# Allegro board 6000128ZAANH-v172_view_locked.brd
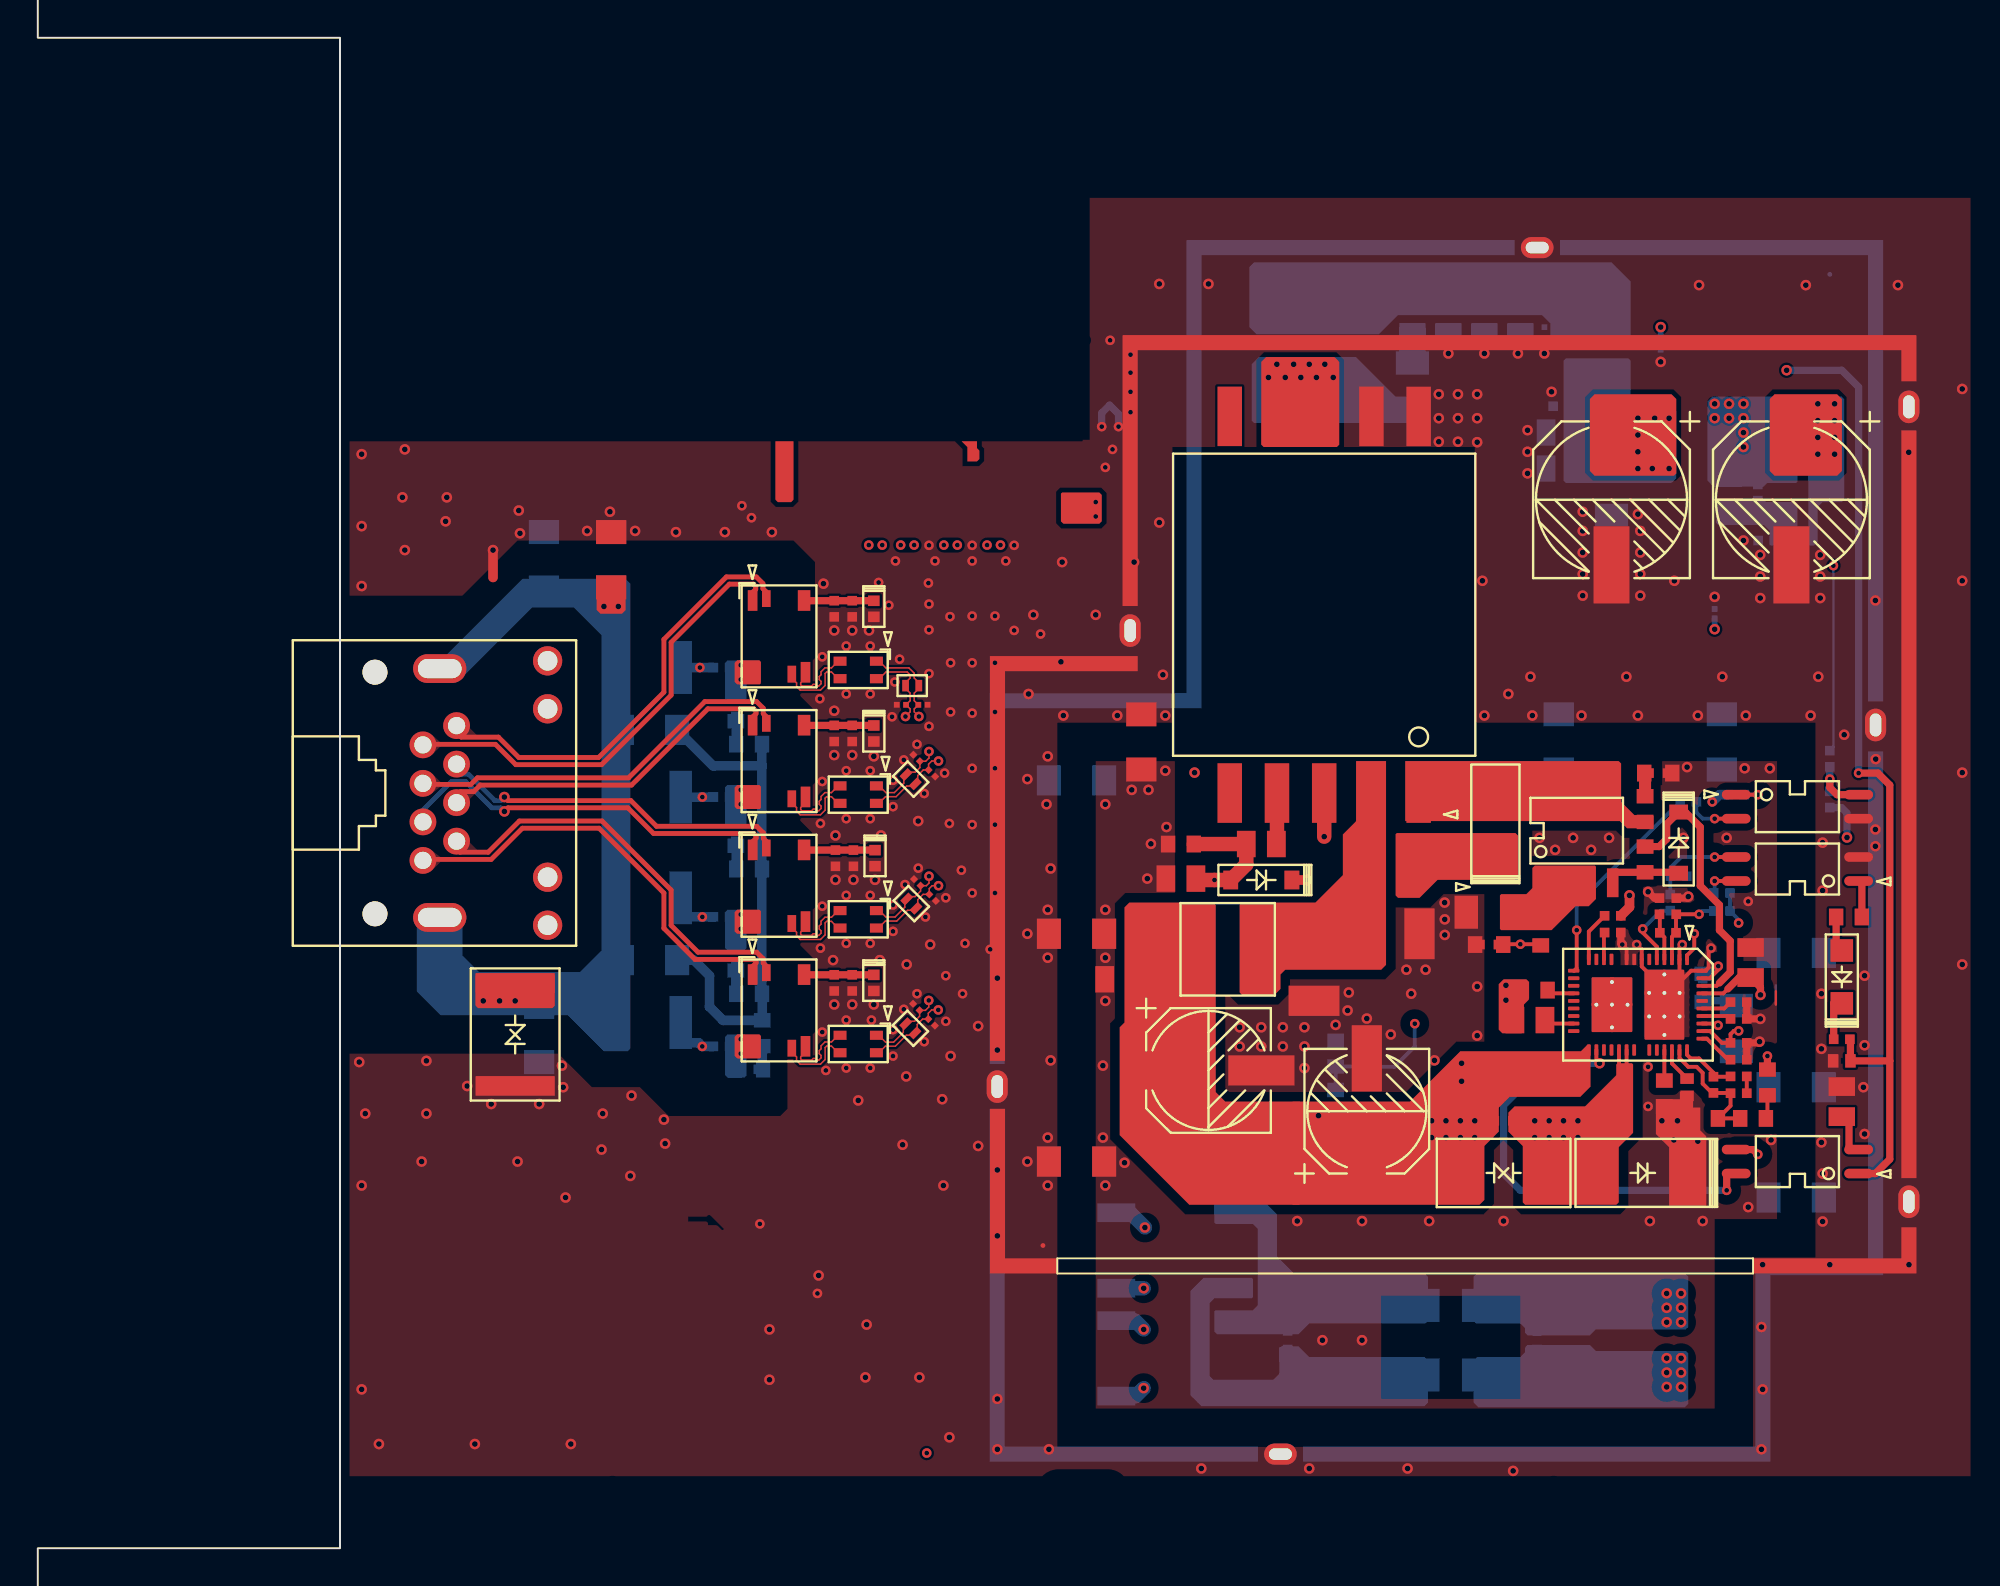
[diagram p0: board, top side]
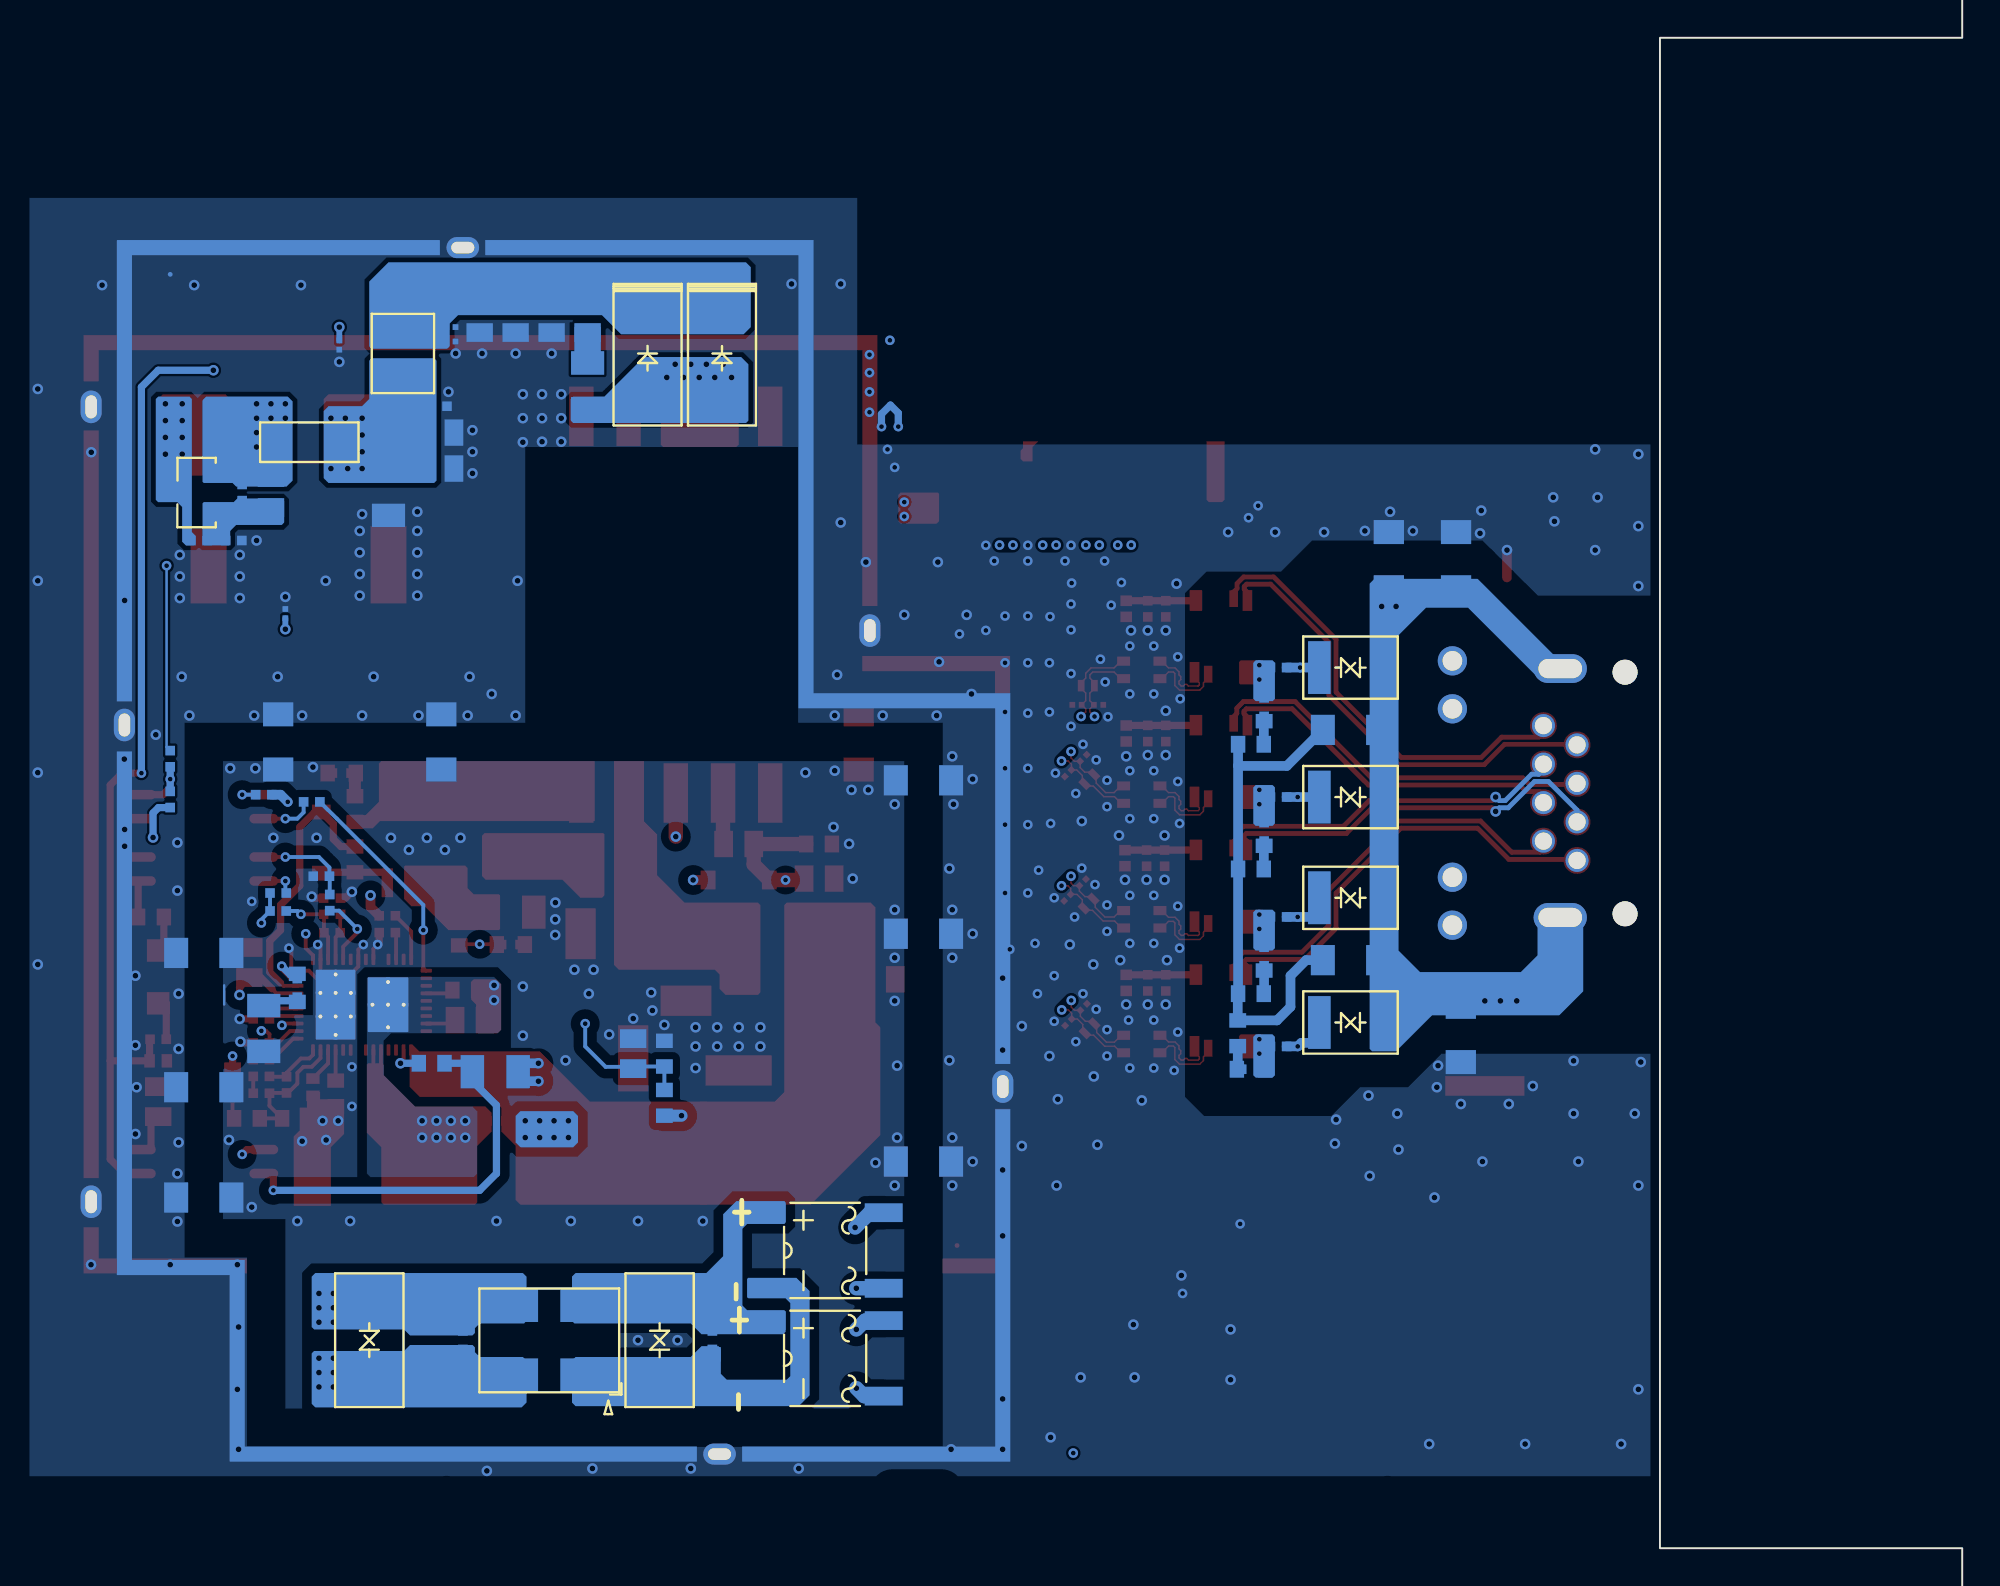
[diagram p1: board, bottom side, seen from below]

Outline 181 x 100 mm; copper layers: TOP, L2, L3, L4, L5, BOTTOM. Coordinates in mm from the lower left corner of the outline.

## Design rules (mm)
constraint set DEFAULT: min track width 0.127
net group 5G_PCIE_RX0: nets 5G_PCIE_RX0_N 5G_PCIE_RX0_P
net group 5G_PCIE_RX_1: nets N17591241 N17591244
net group 5G_PCIE_TX0: nets 5G_PCIE_TX0_N 5G_PCIE_TX0_P
net group 5G_PCIE_TX0-2: nets N5381196 N5381250
net group 5G_PCIE_TX_1: nets N17578663 N17578680
net group GTP_A: nets GTP_AN GTP_AP
net group GTP_B: nets GTP_BN GTP_BP
net group GTP_C: nets GTP_CN GTP_CP
net group GTP_D: nets GTP_DN GTP_DP
net group M_D: nets M_DM M_DP
net group M_DP: nets M_DP+ M_DP-
net group MDI_CH0: nets MDI_CH0_N MDI_CH0_P
net group MDI_CH1: nets MDI_CH1_N MDI_CH1_P
net group MDI_CH2: nets MDI_CH2_N MDI_CH2_P
net group MDI_CH3: nets MDI_CH3_N MDI_CH3_P
net group MDI_CH3_TRX0: nets MDI_CH3_TRXN0 MDI_CH3_TRXP0
net group MDI_CH3_TRX1: nets MDI_CH3_TRXN1 MDI_CH3_TRXP1
net group MDI_CH3_TRX2: nets MDI_CH3_TRXN2 MDI_CH3_TRXP2
net group MDI_CH3_TRX3: nets MDI_CH3_TRXN3 MDI_CH3_TRXP3
net group PCIE_HSO: nets PCIE_HSON PCIE_HSOP
net group PCIE_REFCLK: nets PCIE_REFCLK_N PCIE_REFCLK_P
net group PCIE_REFCLK-2: nets N5381146 N5381180
net group USB-PD: nets USB-PD_CC1 USB-PD_CC2
net group USB_D: nets USB_D+ USB_D-
net group EGND: nets EAR_GND
net group RF50: nets BLE_RFIO N32329 N32649 N49495 N49503
net group S15: nets N17720182 N17720684 N17720687 N17720690 N17720693 N17720696

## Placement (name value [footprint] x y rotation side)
C6  1000 PF/2KV  [C1206-0160]  26.8 62.36 90 bottom
C11  1000 PF/2KV  [C1206-0160]  30.35 62.36 90 top
C24  1000 PF/2KV  [C1206-0160]  26.54 37.21 270 bottom
C25  2200 PF/2KV  [C1206-0160]  32.38 41.15 180 bottom
C26  2200 PF/2KV  [C1206-0160]  32.38 53.34 180 bottom
C51  0.1 UF/25V  [C0402]  93.34 63.37 0 bottom
C61  33 PF/25V  [C0201]  80.01 73.91 180 bottom
C62  100 PF/50V  [C0201]  80.01 74.68 180 bottom
C63  2 PF/25V  [C0201]  46.86 54.67 0 top
C64  2 PF/25V  [C0201]  45.72 54.67 180 top
C65  2 PF/25V  [C0201]  46.52 51.85 135 top
C66  2 PF/25V  [C0201]  47.33 51.05 315 top
C67  2 PF/25V  [C0201]  46.56 45.27 135 top
C68  2 PF/25V  [C0201]  47.37 44.46 315 top
C69  2 PF/25V  [C0201]  46.51 38.66 135 top
C70  2 PF/25V  [C0201]  47.32 37.85 315 top
C72  1200 PF/50V  [C0603]  85.79 51.05 0 top
C75  1000 PF/2KV  [C1206-0160]  30.35 62.36 90 bottom
C82  0.1 UF/6.3V  [C0201]  88.77 59.5 90 bottom
C84  1000 PF/2KV  [C1206-0160]  93.09 34.42 0 bottom
C88  0.1 UF/6.3V  [C0201]  85.92 73.72 270 bottom
C99  1000 PF/2KV  [C1206-0160]  58.42 52.7 90 top
C100  1000 PF/2KV  [C1206-0160]  80.52 52.7 90 bottom
C101  1000 PF/2KV  [C1206-0160]  54.99 30.48 180 bottom
C102  1000 PF/2KV  [C1206-0160]  54.99 30.48 180 top
C103  1000 PF/2KV  [C1206-0160]  54.99 42.55 180 top
C104  1000 PF/2KV  [C1206-0160]  89.15 52.7 90 bottom
C105  1000 PF/2KV  [C1206-0160]  54.99 42.55 180 bottom
C106  1000 PF/2KV  [C1206-0160]  93.09 41.53 0 bottom
C215  0.01 UF/100V  [C0603]  66.17 21.02 270 bottom
C218  0.01 UF/100V  [C0603]  79.38 21.02 270 bottom
C236  22UF/63V  [CES-0630-P-0850-G]  61.98 35.31 0 top
C238  0.01 UF/100V  [C0603]  36.96 54.55 90 bottom
C243  22UF/63V  [CES-0630-P-0850-G]  70.36 33.15 90 top
C335  1000 PF/2KV  [C1206-0160]  93.09 28.57 0 bottom
C338  1000 PF/2KV  [C1206-0160]  54.99 50.67 180 bottom
C339  2200 PF/100V  [C0805]  72.77 75.18 90 bottom
C340  22 UF/25V  [C0805]  78.49 75.18 270 bottom
C343  22 UF/25V  [C0805]  76.58 75.18 270 bottom
C344  22 UF/25V  [C0805]  74.68 75.18 270 bottom
C358  0.1 UF/25V  [C0402]  80.64 70.48 180 bottom
C360  22 UF/25V  [C0805]  80.64 69.09 180 bottom
C361  0.01 UF/100V  [C0603]  36.96 47.94 90 bottom
C362  22 UF/25V  [C0805]  80.64 67.18 180 bottom
C363  0.01 UF/100V  [C0603]  36.96 41.34 90 bottom
C367  0.01 UF/100V  [C0603]  37.66 35.37 180 bottom
C371  0.1 UF/100V  [C0603]  77.6 32.64 180 top
C374  0.1 UF/100V  [C0805]  70.36 36.2 270 bottom
C375  0.1 UF/100V  [C0805]  57.28 40.13 0 top
C376  2.2 UF/100V  [C1210]  67.56 40.39 90 top
C377  2.2 UF/100V  [C1210]  71.75 42.55 180 top
C378  0.1 UF/100V  [C0805]  71.63 47.12 180 top
C379  4.7 UF/25V  [C0805]  90.68 41.02 270 top
C400  0.1 UF/16V  [C0402]  42.16 59.76 90 top
C401  0.1 UF/16V  [C0402]  42.16 53.15 90 top
C402  0.1 UF/16V  [C0402]  42.23 46.55 90 top
C403  0.1 UF/16V  [C0402]  42.16 39.94 90 top
C410  4700 PF/50V  [C0402]  90.04 34.99 0 top
C412  10 PF/50V  [C0402]  88.71 34.54 270 top
C413  0.1 UF/25V  [C0402]  90.04 36.77 0 top
C414  330 PF/50V  [C0603]  76.83 41.97 0 top
C416  4.7 UF/25V  [C0805]  60.52 45.47 180 top
C420  0.047 UF/50V  [MLCC-0120X0070]  87.31 34.42 270 top
C434  390 PF/50V  [C0402]  43.12 59.76 90 top
C449  0.1 UF/50V  [MLCC-0120X0070]  95.5 35.81 180 top
C450  390 PF/50V  [C0402]  43.12 53.15 90 top
C451  390 PF/50V  [C0402]  43.18 46.55 90 top
C452  390 PF/50V  [C0402]  43.12 39.94 90 top
C608  4.7 UF/25V  [C0805]  89.53 65.91 270 bottom
C745  0.1 UF/25V  [C0402]  90.04 38.93 0 top
C746  1000 PF/50V  [C0603]  88.14 39.68 90 bottom
C747  2200 PF/50V  [C0402]  86.74 44.01 270 top
D3  SM1200AM-C  [DOS-SMAM-SECOS]  77.16 48.55 90 top
D5  1N4148W  [DOS-SOD-123-GRANDE]  86.87 47.37 270 top
D7  SK5100BM-C  [DOS-SMBM-SECOS]  69.6 73.03 270 bottom
D8  MMSZ6V8CW-C  [DOS-SOD-123LH-SECOS]  95.5 40.26 90 top
D15  1N4148W  [DOS-SOD-123-GRANDE]  64.77 45.39 180 top
D17  SK5100BM-C  [DOS-SMBM-SECOS]  65.66 73.03 270 bottom
D25  SK5100BM-C  [DOS-SMBM-SECOS]  84.97 29.88 180 top
D53  TTB210SR-C  [BRS-TFS-SECOS]  60.2 20.06 90 bottom
D57  TTB210SR-C  [BRS-TFS-SECOS]  60.2 25.77 90 bottom
D61  AZ5525-01F.R7G  [VARS-DFN1006P2X-AMAZING]  44.26 59.76 270 top
D62  AZ5525-01F.R7G  [VARS-DFN1006P2X-AMAZING]  44.26 53.15 270 top
D63  AZ5525-01F.R7G  [VARS-DFN1006P2X-AMAZING]  44.32 46.55 270 top
D64  AZ5525-01F.R7G  [VARS-DFN1006P2X-AMAZING]  44.26 39.94 270 top
D79  BV-FA2.5UCB  [VARS-DFN1006-BENCENT]  46.29 55.69 180 top
D80  BV-FA2.5UCB  [VARS-DFN1006-BENCENT]  46.21 50.73 315 top
D81  BV-FA2.5UCB  [VARS-DFN1006-BENCENT]  46.25 44.14 315 top
D82  BV-FA2.5UCB  [VARS-DFN1006-BENCENT]  46.19 37.54 315 top
EC4  220 UF/25V  [CES-0800-P-0950-G]  92.84 65.53 270 top
EC5  220 UF/25V  [CES-0800-P-0950-G]  83.31 65.53 270 top
FB13  BBPY00321611101Y00  [FILTS-BBPY00321611]  87.5 68.58 180 bottom
FB20  HFZ1005PF-121T20  [FILTS-0402]  36.2 56.64 180 bottom
FB21  HFZ1005PF-121T20  [FILTS-0402]  36.2 49.79 180 bottom
FB22  HFZ1005PF-121T20  [FILTS-0402]  36.2 43.44 180 bottom
FB23  HFZ1005PF-121T20  [FILTS-0402]  36.2 36.58 180 bottom
L2  WCM5555FASV-142-LM  [LS-WCM5555]  74.8 21.01 0 bottom
L3  1 uH/6.2A Irms  [LS-TMIM3225]  82.55 73.28 270 bottom
L5  10 uH/2A Irms /3.12A Isat  [LS-AHP40XX]  62.99 41.72 0 top
L45  WCM2012F2SF-801-GZ  [LS-2012F2SF]  43.43 56.52 180 top
L46  WCM2012F2SF-801-GZ  [LS-2012F2SF]  43.43 49.91 180 top
L47  WCM2012F2SF-801-GZ  [LS-2012F2SF]  43.43 43.31 180 top
L48  WCM2012F2SF-801-GZ  [LS-2012F2SF]  43.43 36.71 180 top
NOREF  -  []  56.01 -10.16 0 top
NOREF#2  -  []  -8.76 -39.37 0 top
NOREF#3  -  []  154.43 -10.16 0 top
NOREF#4  -  []  195.71 -10.16 0 top
NOREF#5  -  []  -8.76 -10.16 0 top
NOREF#6  -  []  -15.88 213.36 0 top
NOREF#7  -  []  -85.6 -76.2 0 top
NOREF#8  -  []  108.71 -10.16 0 top
NOREF#9  -  []  198.12 213.36 0 top
NOREF#10  -  []  0 0 0 top
NOREF#11  -  []  -15.88 -6.35 0 top
P1  PJ-04-4026-V5112-9  [RJ45-PJ-04-4026-V511X-PIP]  17.85 50 270 top
Q3  SSG06N15V-C  [SOP8-0600-1270-9]  81.47 48.01 0 top
Q32  SMS3407-C  [SOT-23-SGD]  93.47 65.91 90 bottom
R83  20 OHM  [R0603]  85.09 49.15 90 top
R139  10 OHM  [R1206]  72.77 71.56 90 bottom
R141  2 K  [R0603]  95.89 43.43 180 top
R147  3.3 K  [R0402]  95.5 36.96 180 top
R148  4.7 K  [R0805]  95.5 33.66 90 top
R149  13.7 K  [R1206]  77.66 35.24 0 bottom
R151  11.8 K  [R0603]  81.03 35.69 0 bottom
R158  24.9 K  [R1206]  81.15 21.02 270 bottom
R172  4.7 K  [R0402]  89.92 49.91 0 bottom
R180  4.7 K  [R0402]  94.87 49.66 270 bottom
R216  10 K  [R1206]  83.31 65.91 270 bottom
R237  75 OHM  [R0603]  37.66 52.58 0 bottom
R241  0 OHM  [R0402]  94.87 51.82 90 bottom
R242  75 OHM  [R0603]  38.35 37.27 90 bottom
R243  75 OHM  [R0603]  37.66 45.98 0 bottom
R244  75 OHM  [R0603]  37.66 39.37 0 bottom
R274  0 OHM  [R1206]  74.8 22.86 0 bottom
R275  0 OHM  [R1206]  74.8 19.18 0 bottom
R291  110 K  [R0603]  68.71 33.59 270 bottom
R292  20 K  [R0603]  68.71 36.2 270 bottom
R293  60.4 K  [R0402]  85.85 44.01 270 top
R294  49.9 K  [R0603]  79.25 39.56 180 top
R296  499 K  [R0603]  86.11 34.09 90 top
R297  3.3 K  [R0603]  60.52 47.3 0 top
R298  24.9 K  [R0603]  90.81 32.77 0 top
R299  10 OHM  [R0603]  91.57 34.67 90 top
R300  4.32 K  [R0603]  88.27 32.77 0 top
R301  100 K  [R0402]  90.04 34.1 0 top
R302  0 OHM  [R0402]  90.04 35.88 180 top
R303  4.7 OHM  [R0603]  85.09 46.48 90 top
R304  0.12 OHM  [R1206]  76.83 43.69 0 top
R305  1 K  [R0603]  79.57 42.61 270 top
R306  240 K  [R0402]  86.3 42.6 0 top
R307  31.6 OHM  [R0805]  78.99 37.97 180 top
R308  10 K  [R0402]  83.38 43.5 0 top
R310  10 K  [R0402]  89.15 44.7 0 bottom
R311  100 K  [R0402]  86.87 45.59 180 bottom
R312  39 K  [R0805]  71.63 45.27 180 top
R313  3.9 OHM  [R0805]  64.77 47.3 180 top
R314  51 OHM  [R1206]  89.92 37.53 90 bottom
R315  0 OHM  [R0402]  83.38 42.61 0 top
R316  0 OHM  [R0402]  86.42 44.2 90 bottom
R317  0 OHM  [R0402]  89.15 43.75 180 bottom
R322  0 OHM  [R0402]  87.38 49.53 0 bottom
R336  0 OHM  [R0402]  90.04 38.04 0 top
R615  300 K  [R0402]  91.06 65.91 270 bottom
R616  30 K  [R0402]  91.5 63.37 180 bottom
RV22  BV-SMBJ58C2  [VARS-SMB-BENCENT]  68.96 21.02 90 bottom
RV24  BV-SMBJ58C2  [VARS-SMB-BENCENT]  84.33 21.02 90 bottom
RV31  BV-SMBJ58C2  [VARS-SMB-BENCENT]  77.6 29.88 180 top
RV35  MLVS1210H48142  [VARS-MLVS1210]  32.38 56.64 0 bottom
RV36  MLVS1210H48142  [VARS-MLVS1210]  32.38 49.78 0 bottom
RV37  MLVS1210H48142  [VARS-MLVS1210]  32.38 44.45 0 bottom
RV38  MLVS1210H48142  [VARS-MLVS1210]  32.38 37.85 0 bottom
RV51  BN362M  [VARS-BN]  25.27 37.21 90 top
SC1  POE_TOP_COVER  [SHIELD-COVER]  53.21 26.04 270 top
SC2  POE_BOT_COVER  [SHIELD-COVER]  94.87 77.47 270 bottom
SF1  POE_TOP_FRAME  [SHIELD-04825X04890-TEST]  74.93 49.4 0 top
SF2  POE_BOT_FRAME  [SHIELD-06390X04650-TEST]  74.04 46.94 180 bottom
T3  PH2512-007SR  [TRS10-PH2512-007SX]  68.1 59.97 0 top
T6  TXF453229NF-181-G  [TRS6-TXF453229]  39.24 58.3 270 top
T7  TXF453229NF-181-G  [TRS6-TXF453229]  39.24 51.69 270 top
T8  TXF453229NF-181-G  [TRS6-TXF453229]  39.24 45.09 270 top
T9  TXF453229NF-181-G  [TRS6-TXF453229]  39.24 38.48 270 top
U40  LTV-217-B-G  [SOP4-0700-1270]  93.15 49.28 270 top
U41  LTV-217-B-G  [SOP4-0700-1270]  93.15 45.97 90 top
U42  LTV-217-B-G  [SOP4-0700-1270]  93.15 30.48 90 top
U50  TPS23731RMTR  [QFN45-0700X0500-0400-VIA-H8]  84.71 38.79 270 top

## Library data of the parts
C6 C11 C24-C26 C51 C61-C70 C75 C82 C84 C88 C99-C106 C215 C218 C238 C335 C338-C340 C343 C344 C358 C360-C363 C367 C371 C374-C379 C400-C403 C410 C412-C414 C416 C420 C434 C449-C452 C608 C745-C747 = CAP-NP
C72 = CAP NP
C236 C243 = CAP
D3 D5 D7 D15 D17 D25 = DIODE_1
D8 = ZENER-DIODE
D53 D57 = MD5SBRIDGE
D61-D64 RV22 RV24 RV31 RV35-RV38 = VAR-2PIN
D79-D82 = VARISTOR
EC4 EC5 = CAP_1
FB13 FB20-FB23 = FILTER-2PIN
L2 = UT21332V-TS
L3 L5 = INDUCTOR
L45-L48 = COMMON_CHOKE_12-43
P1 = RJ45-8PIN8C+2LED+2G1-2
Q3 = MOSFET-N -8PIN
Q32 = MOSFET-P
R83 R139 R147 R149 R151 R158 R172 R180 R216 R237 R241-R244 R274 R275 R291-R294 R296-R299 R301-R308 R310-R317 R322 R336 R615 R616 = RESISTOR
R141 R148 R300 = Resistor-2
RV51 = VAR
SC1 SC2 = SHIELD-COVER
SF1 = 3-PIN_6
SF2 = 3-PIN_5
T3 = PH2512-007SR
T6-T9 = TXF453229NF-181-G
U40-U42 = LTV-817A
U50 = TPS23731_0

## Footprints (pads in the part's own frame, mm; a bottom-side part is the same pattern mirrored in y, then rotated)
BRS-TFS-SECOS
  rect 0.991x2.007 smd: AC1(-2,-3.1) AC2(2,-3.1) DC+(2,3.1) DC-(-2,3.1)
C0201
  rect 0.305x0.305 smd: 1(-0.246,0) 2(0.246,0)
C0402
  rect 0.508x0.508 smd: 1(-0.429,0) 2(0.429,0)
C0603
  custom 0.222x0.222 smd: 1(-0.681,0) 2(0.681,0)
C0805
  rect 0.991x1.397 smd: 1(-0.795,0) 2(0.795,0)
C1206-0160
  rect 1.27x1.6 smd: 1(-1.463,0) 2(1.463,0)
C1210
  rect 1.6x2.692 smd: 1(-1.39,0) 2(1.39,0)
CES-0630-P-0850-G
  rect 3.505x1.6 smd: 1(-2.8,0) 2(2.8,0)
CES-0800-P-0950-G
  rect 4.089x1.905 smd: 1(-3.45,0) 2(3.45,0)
DOS-SMAM-SECOS
  rect 1.6x1.803 smd: A(1.9,0) C(-1.9,0)
DOS-SMBM-SECOS
  rect 1.803x2.54 smd: A(2.4,0) C(-2.4,0)
DOS-SOD-123-GRANDE
  rect 0.787x0.991 smd: A(1.62,0) C(-1.62,0)
DOS-SOD-123LH-SECOS
  rect 1.194x1.194 smd: A(1.4,0) C(-1.4,0)
FILTS-0402
  rect 0.508x0.508 smd: 1(-0.429,0) 2(0.429,0)
FILTS-BBPY00321611
  rect 1.245x1.6 smd: 1(-1.725,0) 2(1.725,0)
LS-2012F2SF
  rect 0.686x0.483 smd: 1(-0.962,-0.463) 2(0.962,-0.463) 3(0.962,0.463) 4(-0.962,0.463)
LS-AHP40XX
  rect 1.499x4.394 smd: 1(-1.5,0) 2(1.5,0)
LS-TMIM3225
  rect 1.499x2.794 smd: 1(-1.1,0) 2(1.1,0)
LS-WCM5555
  rect 1.803x1.194 smd: 1(-2.55,1.55) 2(-2.55,-1.55) 3(2.55,-1.55) 4(2.55,1.55)
MLCC-0120X0070
  rect 0.559x0.711 smd: 1(-0.457,0) 2(0.457,0)
QFN45-0700X0500-0400-VIA-H8
  custom 0.05x0.05 smd: 1(-2.4,2.6) 2(-2.4,2.2) 3(-2.4,1.8) 4(-2.4,1.4) 5(-2.4,1) 6(-2.4,0.6) 7(-2.4,0.2) 8(-2.4,-0.2) 9(-2.4,-0.6) 10(-2.4,-1.4) 11(-2.4,-1.8) 12(-2.4,-2.2) 13(-2.4,-2.6) 14(-1.8,-3.4) 15(-1.4,-3.4) 16(-1,-3.4) 17(-0.6,-3.4) 18(-0.2,-3.4) 19(0.2,-3.4) 20(0.6,-3.4) 21(1,-3.4) 22(1.4,-3.4) 23(2.4,-2.6) 24(2.4,-2.2) 25(2.4,-1.8) 26(2.4,-1.4) 27(2.4,-1) 28(2.4,-0.6) 29(2.4,-0.2) 30(2.4,0.6) 31(2.4,1) 32(2.4,1.4) 33(2.4,1.8) 34(2.4,2.2) 35(2.4,2.6) 36(1.8,3.4) 37(1.4,3.4) 38(1,3.4) 39(0.6,3.4) 40(0.2,3.4) 41(-0.2,3.4) 42(-0.6,3.4) 43(-1,3.4) 44(-1.4,3.4) 45(-1.8,3.4)
  custom 0.525x0.525 smd: 46(0,1.4)
  custom 0.537x0.537 smd: 47(0,-1.375)
  round 0.508 hole 0.203: 48(-0.625,2.205) 49(0.625,2.205) 50(-1.6,1.4) 51(-0.625,1.4) 52(0.625,1.4) 53(1.6,1.4) 54(-0.625,0.595) 55(0.625,0.595) 56(0,-0.55) 57(-1.2,-1.375) 58(0,-1.375) 59(1.2,-1.375) 60(0,-2.2)
R0402
  rect 0.508x0.508 smd: 1(-0.429,0) 2(0.429,0)
R0603
  rect 0.762x0.889 smd: 1(-0.681,0) 2(0.681,0)
R0805
  rect 0.991x1.397 smd: 1(-0.795,0) 2(0.795,0)
R1206
  rect 1.245x1.753 smd: 1(-1.212,0) 2(1.212,0)
RJ45-PJ-04-4026-V511X-PIP
  round 1.321 hole 1.321 unplated: (-6.4,0) (6.4,0)
  round 1.422 hole 0.914: 1(3.57,2.54) 2(2.55,4.32) 3(1.53,2.54) 4(0.51,4.32) 5(-0.51,2.54) 6(-1.53,4.32) 7(-2.55,2.54) 8(-3.57,4.32)
  oval 1.524x2.819 hole 1.016x2.311: G1(6.59,3.43) G2(-6.59,3.43)
  round 1.549 hole 1.041: LA(-7,9.14) LC(-4.46,9.14) RA(4.46,9.14) RC(7,9.14)
SHIELD-04825X04890-TEST
  oval 1.118x1.727 hole 0.61x1.219: 1(-17.1,9.2) 2(24.124,21.05) 3(24.124,-21.05)
SHIELD-06390X04650-TEST
  oval 1.118x1.727 hole 0.61x1.219: 1(23.25,-12.486) 2(-23.25,6.666)
  oval 1.727x1.118 hole 1.219x0.61: 3(-5.336,31.95) 4(8.257,-31.95)
SHIELD-COVER
  round 0.254 smd: 1(0,0)
SOP4-0700-1270
  oval 0.508x1.524 smd: 1(-0.635,-3.24) 2(0.635,-3.24) 3(0.635,3.24) 4(-0.635,3.24)
SOP8-0600-1270-9
  rect 0.61x1.524 smd: 1(-1.905,-2.76) 2(-0.635,-2.76) 3(0.635,-2.76) 4(1.905,-2.76) 5(1.905,2.76) 6(0.635,2.76) 7(-0.635,2.76) 8(-1.905,2.76)
SOT-23-SGD
  rect 0.762x1.397 smd: D(0,1.05) G(-0.95,-1.05) S(0.95,-1.05)
TRS6-TXF453229
  rect 1.092x0.508 smd: 1(-1.9,-1.4) 4(1.9,1.4)
  rect 0.889x0.457 smd: 2(-2,-0.675) 5(2,0.675)
  rect 1.092x0.66 smd: 3(-1.9,1.325) 6(1.9,-1.325)
TRS10-PH2512-007SX
  rect 1.295x3.15 smd: 1(5,-9.975) 2(2.5,-9.975) 3(0,-9.975) 4(-2.5,-9.975) 5(-5,-9.975) 6(-5,9.975) 7(-2.5,9.975) 8(0,9.975) 9(2.5,9.975) 10(5,9.975)
VARS-BN
  rect 1.041x4.191 smd: 1(-2.725,0) 2(2.725,0)
VARS-DFN1006-BENCENT
  rect 0.356x0.61 smd: 1(-0.35,0) 2(0.35,0)
VARS-DFN1006P2X-AMAZING
  rect 0.559x0.61 smd: 1(-0.425,0) 2(0.425,0)
VARS-MLVS1210
  rect 1.194x2.794 smd: 1(-1.65,0) 2(1.65,0)
VARS-SMB-BENCENT
  rect 2.159x2.743 smd: 1(-2.21,0) 2(2.21,0)

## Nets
GND: C6.2 C11.2 C24.2 C61.2 C62.2 C63.2 C64.2 C65.2 C66.2 C67.2 C68.2 C69.2 C70.2 C75.2 C82.2 C84.2 C88.2 C99.2 C100.2 C101.2 C102.2 C103.2 C104.2 C105.2 C106.2 C335.2 C338.2 C340.2 C343.2 C344.2 C358.2 C360.2 C362.2 C400.1 C401.1 C402.1 C403.1 C434.1 C449.2 C450.1 C451.1 C452.1 D61.2 D62.2 D63.2 D64.2 EC4.2 EC5.2 R148.2 R216.2 R616.2 RV51.1 SC1.1 SC2.1 SF1.1 SF1.2 SF1.3 SF2.1 SF2.2 SF2.3 SF2.4 T3.9 T3.10 U40.3 U41.2
PGND: C72.2 C84.1 C99.1 C100.1 C101.1 C102.1 C103.1 C104.1 C105.1 C106.1 C236.2 C243.2 C335.1 C338.1 C374.1 C375.1 C376.1 C377.1 C379.1 C413.2 C414.1 C416.2 C420.2 C745.2 C747.1 D25.C R292.1 R293.1 R296.1 R297.1 R300.1 R302.1 R304.1 R311.1 R314.1 R315.2 R336.2 U50.2 U50.7 U50.8 U50.9 U50.45 U50.46 U50.48 U50.49 U50.50 U50.51 U50.52 U50.53 U50.54 U50.55
VBUS_9_15V_IN: C449.1 R147.1 U42.1
VCC: C379.2 D15.C R172.1 R308.2 U50.42
VCC_3V3: C82.1
VCC_9_15V: C51.2 EC4.1 Q32.D
VDD_1V8: R180.2
VDD_B: C218.1 C236.1 C243.1 C371.2 C375.2 L2.3 L5.1 R149.1 R158.1 R274.2 R291.2 RV24.2 RV31.2 U50.23
VSS: C218.2 C371.1 D25.A L2.4 R158.2 R275.2 R294.2 R307.2 RV24.1 RV31.1 U42.3 U50.27 U50.28(VSS_2) U50.47 U50.56 U50.57 U50.58 U50.59 U50.60
APD: R316.1 U50.5
APDO: R308.1 U50.13
AUX_3V3: C88.1
CP: C746.2 T3.3 U50.44
CS: C414.2 R305.2 U50.1
DTHR: C747.2 R306.2 R317.2 U50.3
EAR_GND: C6.1 C11.1 C24.1 C25.2 C26.2 C75.1 P1.G1 P1.G2 RV35.1 RV36.1 RV37.1 RV38.1 RV51.2
FRS: R293.2 R306.1 U50.4
LAN_A+: P1.LA
LAN_A-: P1.LC
LAN_G+: P1.RA
LAN_G-: P1.RC
MDI_CH0_N: P1.2 T9.2
MDI_CH0_P: P1.1 T9.1
MDI_CH1_N: P1.6 T8.2
MDI_CH1_P: P1.3 T8.1
MDI_CH2_N: P1.5 T7.2
MDI_CH2_P: P1.4 T7.1
MDI_CH3_N: P1.8 T6.2
MDI_CH3_P: P1.7 T6.1
PAIR12: D53.AC2 FB23.2(N2) RV38.2
PAIR12_FB23: C367.2 FB23.1 T9.6
PAIR36: D53.AC1 FB22.2(N2) RV37.2
PAIR36_FB22: C363.2 FB22.1 T8.6
PAIR45: D57.AC2 FB21.2(N2) RV36.2
PAIR45_FB21: C361.2 FB21.1 T7.6
PAIR78: D57.AC1 FB20.2(N2) RV35.2
PAIR78_FB20: C238.2 FB20.1 T6.6
POE_AT_AF_DET: R241.2
POWER_IN: C608.1 FB13.1 Q32.S R615.1
SS: C420.1 U50.33
T2P: R322.1 U50.14
UV: C374.2 R291.1 R292.2 U50.38
VB: C413.1 R310.2 R317.1 U50.37
VREG: C416.1 D15.A R297.2 R299.2 R313.2
N5282457: R310.1 U41.4
N5282939: D8.C(CATHODE) R147.2
N5283551: R313.1 T3.4
N5284275: R311.2 R316.2 U41.3
N5284681: R172.2 U40.1
N5284715: R180.1 R241.1 U40.4
N5285307: R322.2 U40.2
N5587134: C68.1 D81.2 L47.4
N5587686: C70.1 D82.2 L48.4
N5589036: C65.1 D80.1 L46.1
N17072113: C400.2 C434.2 D61.1 T6.3
N17072503: C63.1 D79.1 L45.1
N17072520: C64.1 D79.2 L45.4
N17072536: L45.2 T6.4
N17072544: L45.3 T6.5
N17073401: C401.2 C450.2 D62.1 T7.3
N17073788: C66.1 D80.2 L46.4
N17073817: L46.2 T7.4
N17073825: L46.3 T7.5
N17074521: C402.2 C451.2 D63.1 T8.3
N17074761: C67.1 D81.1 L47.1
N17074791: L47.2 T8.4
N17075150: C403.2 C452.2 D64.1 T9.3
N17075378: C69.1 D82.1 L48.1
N17075450: L48.2 T9.4
N17075458: L48.3 T9.5
N17419443: C51.1 C608.2 Q32.G R615.2 R616.1
N17426803: C215.2 D53.DC- D57.DC- L2.1 R275.1 RV22.1
N17426807: C215.1 D53.DC+ D57.DC+ L2.2 R274.1 RV22.2
N17430841: R141.1 U41.1
N17430844: D8.A R141.2
N17432429: C61.1 C62.1 C339.2 C340.1 C343.1 C344.1 D7.C D17.C L3.1
N17432448: D7.A D17.A R139.1 T3.7 T3.8
N17432547: C339.1 R139.2
N17432813: C358.1 C360.1 C362.1 EC5.1 FB13.2(N2) L3.2 R216.1
N17439497: C412.2 R298.1 R300.2 R301.1 U50.34
N17439510: C376.2 C377.2 C378.2 L5.2 R312.2 T3.2
N17439514: Q3.1 Q3.2 Q3.3(S_3) R304.2 R305.1
N17439527: C410.2 R301.2
N17439559: C410.1 C412.1 U50.35
N17439609: R302.2 U50.36
N17439696: D3.A Q3.5 Q3.6 Q3.7 Q3.8 R83.1 T3.1
N17439796: R336.1 U50.39
N17439853: D5.A Q3.4 R303.1
N17439860: D5.C R303.2 U50.43
N17439883: C378.1 D3.C R312.1
N17440114: R148.1 U42.2
N17440204: R149.2 R151.1 U42.4
N17440325: R294.1 U50.17
N17440336: R307.1 U50.21
N17440344: R151.2 U50.24
N17440357: R296.2 U50.32
N17440451: C746.1 R314.2
N17440486: R315.1 U50.11
N17440571: R298.2 R299.1
N17440589: C745.1 U50.40
N17592466: C72.1 R83.2
N17603237: L47.3 T8.5
N51055004: C25.1 C26.1 R237.2 R242.2 R243.2 R244.2
N51058661: C238.1 R237.1
N51058667: C361.1 R243.1
N51058675: C363.1 R244.1
N51058681: C367.1 R242.1

Pads without a net: T3 5 6; U50 6 10 12 15 16 18 19 20 22 25 26 29 30 31 41

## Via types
v1: diameter 0.559, hole 0.305, TOP to BOTTOM, 343 vias
v2: diameter 0.508, hole 0.254, TOP to BOTTOM, 155 vias

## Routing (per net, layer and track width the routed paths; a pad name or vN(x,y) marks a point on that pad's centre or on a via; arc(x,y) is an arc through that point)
GND: length 16.6
  TOP w0.508: 24.1,61.42 v1(24.1,62.87)
  L4 w0.102: 78.99,14.61 79.2,14.81 90.83,14.81 90.86,14.84 90.86,14.85 v1(91.25,15.24)
  BOTTOM w0.381: v2(57.21,69.41) 57.21,70.07 56.74,70.54 56.32,70.13 v2(56.32,69.41)
  vias: v1(17.02,35.75) v1(17.14,67.94) v1(17.14,64.14) v1(17.14,60.96) v1(17.14,29.21) v1(17.14,18.41) v1(17.34,33.02) v1(18.06,15.52) v1(19.3,65.66) v1(19.43,68.2) v1(19.43,62.87) v1(20.32,30.48) v1(20.57,35.81) v1(20.57,33.02) v1(21.59,64.39) v1(21.65,65.66) v1(22.73,34.48) v1(23.14,15.52) v1(24,33.53) v1(25.4,30.48) v1(25.46,64.96) v1(25.53,63.75) v1(26.54,33.53) v1(27.75,35.56) v1(27.81,34.42) v1(27.94,28.57) v1(28.22,15.52) v1(29.08,63.88) v1(29.84,31.11) v1(29.91,33.02) v1(30.29,64.9) v1(31.43,33.97) v1(31.37,29.72) v1(31.62,63.88) v1(33.15,32.7) v1(33.21,31.43) v1(33.78,63.82) v1(36.37,63.82) v1(38.73,21.59) v1(38.73,18.92) v1(38.86,63.82) v1(41.34,24.45) v1(41.59,61.09) v1(42.1,41.15) v1(42.16,58.61) v1(42.16,54.36) v1(42.16,52.01) v1(42.23,47.75) v1(42.23,45.4) v1(42.16,38.8) v1(43.12,58.61) v1(43.12,52.01) v1(43.12,38.8) v1(43.18,45.4) v1(43.43,33.72) v1(43.81,19.05) v1(43.88,21.84) v1(44.01,58.61) v1(44.26,51.94) v1(44.32,45.4) v1(44.26,38.8) v1(44.64,47.75) v1(44.58,41.15) v1(45.78,31.37) v1(46,40.92) v1(45.97,34.99) v1(46.61,48.51) v1(46.67,19.05) v1(47.24,41.97) v1(47.88,33.78) v1(47.94,29.21) v1(48.32,36.07) v1(48.26,15.88) v1(49.78,37.66) v1(49.78,31.31) v1(50.8,40.2) v1(50.8,36.39) v1(50.8,30.04) v1(50.8,26.54) v1(50.8,17.91) v1(50.8,15.24) v1(52.39,50.74) v1(52.39,42.55) v1(52.39,30.48) v1(52.45,55.24) v1(52.7,59.44) v1(53.4,49.4) v1(53.47,51.94) v1(53.47,43.81) v1(53.47,41.27) v1(53.47,31.75) v1(53.47,29.21) v1(53.53,15.24) v1(53.62,46) v1(53.62,35.84) v1(54.23,62.23) v1(54.17,56.95) v1(54.29,54.1) v1(56.01,59.44) v1(57.15,54.1) v1(58.04,62.23) v1(59.37,76.96) v1(59.37,64.33) v1(59.56,56.26) v1(59.69,54.1) v1(61.59,14.22) v1(61.98,76.96) v1(67.31,14.22) v1(72.52,14.22) v1(74.17,71.12) v1(74.17,69.85) v1(74.17,68.61) v1(74.68,73.28) v1(75.18,71.12) v1(75.18,69.85) v1(75.18,68.61) v1(76.2,71.12) v1(76.2,69.85) v1(76.2,68.58) v1(76.48,61.24) v1(76.58,73.28) v1(76.58,54.1) v1(77.85,55.24) v1(78.11,14.1) v1(78.36,73.28) v1(78.87,69.22) v1(78.87,68.07) v1(78.87,66.93) v1(79.02,56.16) v1(79.12,54.1) v1(79.76,73.28) v1(80.14,71.25) v1(81.72,54.1) v1(81.79,64.9) v1(81.79,63.88) v1(81.79,62.74) v1(81.79,61.59) v1(81.79,60.45) v1(84.1,56.16) v1(84.71,64.77) v1(84.71,54.1) v1(84.84,63.88) v1(84.84,62.74) v1(84.84,61.59) v1(84.84,60.45) v1(85.92,72.83) v1(86.64,61.24) v1(87.95,76.9) v1(87.88,54.1) v1(88.77,60.39) v1(89.18,56.16) v1(90.3,63.37) v1(90.42,54.1) v1(91.19,62.61) v1(91.19,61.47) v1(91.19,60.33) v1(91.25,21.72) v1(91.31,25.02) v1(91.31,18.41) v1(93.6,76.9) v1(93.85,54.1) v1(94.26,56.16) v1(94.36,62.61) v1(94.36,61.47) v1(94.36,60.33) v1(94.42,39.37) v1(94.42,36.45) v1(94.42,31.5) v1(94.49,47.37) v1(94.49,44.83) v1(94.49,29.84) v1(94.49,27.3) v1(94.87,25.02) v1(95.63,53.09) v1(96.65,34.42) v1(96.71,40.32) v1(96.71,36.64) v1(96.71,31.94) v1(97.28,60.2) v1(97.3,51.8) v1(97.28,48.07) v1(97.28,47.18) v1(98.48,76.9) v1(99.05,68.05) v1(99.06,25.02) v1(101.88,71.4) v1(101.88,61.24) v1(101.88,51.08) v1(101.88,40.92) v2(37.27,65.21) v2(37.78,64.58) v2(38.23,27.18) v2(41.27,23.5) v2(41.4,54.99) v2(41.43,48.39) v2(41.43,41.78) v2(41.53,57.21) v2(41.53,50.61) v2(41.53,44.01) v2(41.53,37.34) v2(41.72,35.31) v2(42.8,57.78) v2(42.8,55.24) v2(42.8,51.18) v2(42.8,48.64) v2(42.8,44.58) v2(42.8,42.04) v2(42.8,37.97) v2(42.8,35.43) v2(44.07,57.78) v2(44.07,55.24) v2(44.07,51.18) v2(44.07,48.64) v2(44.07,44.58) v2(44.07,42.04) v2(44.13,37.97) v2(44.07,35.43) v2(44.51,61.15) v2(45.05,59.94) v2(45.22,54.04) v2(45.28,50.67) v2(45.28,49.28) v2(45.28,44.07) v2(45.28,42.67) v2(45.28,37.47) v2(45.28,36.07) v2(45.4,62.29) v2(45.37,55.88) v2(45.62,57.09) v2(45.85,51.75) v2(45.85,38.54) v2(45.91,45.15) v2(46.55,52.58) v2(46.55,39.37) v2(46.61,46.02) v2(46.93,49.97) v2(46.93,36.83) v2(46.99,43.43) v2(47.15,61.12) v2(47.18,63.12) v2(47.18,60.01) v2(47.18,58.64) v2(47.18,56.32) v2(47.18,53.53) v2(47.5,62.29) v2(48.01,51.05) v2(48.07,44.45) v2(48.07,40.32) v2(48.07,37.91) v2(48.29,59.34) v2(48.32,56.9) v2(48.32,54.29) v2(48.26,48.39) v2(48.9,45.91) v2(48.96,39.37) v2(49.09,42.04) v2(49.47,63.12) v2(49.47,62.29) v2(49.47,59.37) v2(49.47,56.9) v2(49.47,54.23) v2(49.47,51.31) v2(49.47,48.32) v2(49.47,44.7) v2(50.42,41.72) v2(50.67,59.37) v2(50.67,56.9) v2(50.67,54.29) v2(50.67,51.31) v2(50.67,48.32) v2(50.67,44.7) v2(51.24,62.29) v2(51.69,63.12) v2(51.69,58.61) v2(53.09,58.42) v2(56.52,67.25) v2(56.77,73.98) v2(56.9,68.2) v2(57.85,73.22) v2(57.85,72.26) v2(57.85,71.25) v2(57.85,70.17)
PGND: length 16.5
  TOP w0.127: 92.01,39.5 92.01,38.8
  TOP w0.203: U50.9 84.11,41.75 v2(83.88,41.97) ; v2(84.65,41.97) 84.91,41.71 U50.7 84.91,40.81 85.33,40.39 U50.50 86.78,40.39 86.91,40.52 U50.2 86.91,41.82 v2(87.06,41.97) ; v2(88.58,41.78) 88.46,41.66 88.46,40.75 88.29,40.59 U50.45 87.53,40.59 86.92,39.98 U50.48
  TOP w0.381: R302.1 C413.2 91.09,36.77 v1(91.15,36.83) ; v1(85.25,44.77) 85.58,44.43 R293.1 ; v1(87.38,44.51) 87.3,44.43 C747.1 ; C745.2 R336.2 v1(91.19,38.04) ; v2(83.88,41.97) 83.8,42.05 R315.2
  BOTTOM w0.127: 92.01,39.81 92.01,38.8
  BOTTOM w0.381: 83.93,42.02 v2(83.88,41.97)
  vias: v1(56.39,35.56) v1(56.39,31.75) v1(56.52,49.4) v1(56.52,43.81) v1(56.52,41.27) v1(56.52,38.99) v1(56.52,29.21) v1(57.53,30.42) v1(57.91,50.16) v1(58.74,45.47) v1(58.8,50.16) v1(58.93,47.31) v1(59.69,51.18) v1(59.75,48.2) v1(61.24,51.08) v1(63.63,37.59) v1(63.63,36.58) v1(64.77,37.59) v1(64.77,36.58) v1(65.91,37.59) v1(65.91,36.58) v1(66.67,27.33) v1(67.06,37.59) v1(67.06,36.58) v1(67.06,35.43) v1(68.01,21.02) v1(68.71,37.72) v1(69.34,38.48) v1(69.41,39.43) v1(70.1,27.33) v1(70.1,21.02) v1(70.36,38.06) v1(71.63,37.21) v1(72.45,40.64) v1(72.71,39.37) v1(73.47,40.64) v1(73.66,27.33) v1(73.94,35.84) v1(74.48,44.2) v1(74.49,43.31) v1(74.49,42.48) v1(76.2,39.75) v1(76.2,37.15) v1(77.6,27.33) v1(79.5,47.62) v1(80.33,46.99) v1(81.28,47.62) v1(82.23,46.99) v1(83.19,47.62) v1(85.34,27.33) v1(85.98,32.64) v1(86.61,31.62) v1(86.8,32.64) v1(87.12,47.62) v1(87.31,51.37) v1(87.88,31.56) v1(88.14,27.33) v1(89.41,47.62) v1(90.36,51.31) v1(90.55,28.07) v1(91.69,51.31) v1(91.76,31.62) v2(85.25,35.5) v2(85.25,33.4) v2(90.55,44.26)
VBUS_9_15V_IN: length 51.6
  TOP w0.381: 98.04,35.81 98.04,50.42 97.41,51.05 v2(96.39,51.05) ; 98.04,35.81 C449.1 95.96,36.93 R147.1 ; 98.04,35.81 98.04,30.61 97.28,29.84 U42.1
  BOTTOM w0.381: v1(92.58,72.39) 95.5,72.39 96.39,71.5 v2(96.39,51.05)
VCC: length 50.3
  TOP w0.203: U50.42 89.24,39.39 89.47,39.62
  TOP w0.381: 89.47,39.62 90.07,40.23 C379.2 91.2,39.71 v1(91.2,39.31)
  TOP w0.508: v1(84.26,44.58) 84.26,43.96 R308.2 ; v1(67.19,45.39) D15.C
  L4 w0.508: 84.26,48.83 84.96,49.53 v2(88.65,49.53) 89.15,49.53 91.2,47.49 v1(91.2,39.31) ; 84.26,48.83 83.57,49.53 67.25,49.53 66.1,48.39 66.1,45.97 66.69,45.39 v1(67.19,45.39) ; 84.26,48.83 v1(84.26,44.58)
  BOTTOM w0.508: R172.1 89.03,49.91 v2(88.65,49.53)
VCC_3V3: length 0.6
  BOTTOM w0.305: C82.1 v1(88.77,58.67)
  vias: v2(56.01,65.41) v2(56.01,64.65)
VCC_9_15V:
  vias: v1(94.23,70.61) v1(94.23,69.72) v1(94.23,68.83) v1(94.23,67.94) v1(95.12,70.61) v1(95.12,69.72) v1(95.12,68.83) v1(95.12,67.94)
VDD_1V8: length 2.3
  BOTTOM w0.381: R180.2 95.49,49.23 95.78,48.94 v1(95.78,47.64)
VDD_B: length 3.6
  BOTTOM w0.508: v1(75.37,35.69) 76.14,35.69 76.45,35.38 R149.1 76.45,35.05 76.14,34.73 v1(75.37,34.73)
  BOTTOM w0.635: R291.2 v1(67.8,32.91)
  vias: v1(73.79,32.64) v1(73.79,31.75) v1(74.55,32.64) v1(74.55,31.75) v1(75.31,32.64) v1(75.31,31.75) v1(76.07,32.64) v1(76.07,31.75) v1(86.23,23.5) v1(86.23,22.73) v1(86.23,21.97) v1(87,23.5) v1(87,22.73) v1(87,21.97)
VSS: length 10.1
  TOP w0.203: U50.27 83.71,35.58 83.69,35.56 ; U50.28 84.11,35.59 84.14,35.56
  TOP w0.381: v2(91.06,30.86) 90.81,31.11 U42.3
  L3 w0.381: v2(91.06,30.86) 90.81,30.61 83.95,30.61
  vias: v1(77.72,39.81) v1(77.72,39.03) v1(79.25,32.64) v1(79.25,31.75) v1(80.01,32.64) v1(80.01,31.75) v1(80.77,32.64) v1(80.77,31.75) v1(81.53,32.64) v1(81.53,31.75) v1(86.23,20.07) v1(86.23,19.3) v1(86.23,18.54) v1(87,20.07) v1(87,19.3) v1(87,18.54)
APD: length 3.8
  TOP w0.203: v2(84.96,42.8) 84.96,42.61 85.71,41.86 U50.5
  BOTTOM w0.203: v2(84.96,42.8) 85.93,43.77 R316.1
APDO: length 2.7
  TOP w0.203: R308.1 82.11,42.66 U50.13
AUX_3V3: length 0.7
  BOTTOM w0.305: C88.1 v1(85.92,74.68)
CP: length 30.6
  TOP w0.203: U50.44 88.51,40.19 88.97,40.65 88.97,40.83 v2(88.96,40.83)
  TOP w0.762: T3.3 v1(68.1,47.69)
  L4 w0.203: v1(68.1,47.69) 74.49,47.69 75.95,46.23 75.95,42.16 76.71,41.4 87.76,41.4 88.33,40.83 v2(88.96,40.83)
  BOTTOM w0.381: v2(88.96,40.83) 88.49,40.36 C746.2
CS: length 14.6
  TOP w0.203: C414.2 77.53,41.99 v2(78.49,41.99) 79.5,41.99 R305.2 ; U50.1 87.31,41.4 87.69,41.78 v2(87.69,42.55)
  L4 w0.203: v2(87.69,42.55) 86.68,43.56 78.87,43.56 78.49,43.18 v2(78.49,41.99)
DTHR: length 4.5
  TOP w0.203: U50.3 86.51,42.38 R306.2 86.73,43.56 C747.2 v2(87.95,43.58)
  BOTTOM w0.203: v2(87.95,43.58) 88.12,43.75 R317.2
EAR_GND:
  vias: v1(23.58,38.99) v1(24.45,38.99) v1(25.27,38.99) v1(29.97,59.88) v1(30.73,59.88)
FRS: length 2.5
  TOP w0.203: U50.4 86.11,42.36 R306.1 85.87,43.56 R293.2
LAN_A+: length 13.1
  L4 w0.203: P1.LA 26.61,57.38 26.61,64.9 29.34,67.63 30.54,67.63
LAN_A-: length 16.8
  L4 w0.203: P1.LC 28.05,55.52 28.05,57.48 26.99,58.55 26.99,64.77 29.34,67.12 30.92,67.12 31.43,67.63
LAN_G+: length 28.2
  L4 w0.203: P1.RA 28.38,46.94 28.38,57.72 27.37,58.74 27.37,64.64 29.46,66.74 33.34,66.74 34.23,67.63
LAN_G-: length 31.3
  L4 w0.203: 35.12,67.63 33.85,66.36 29.59,66.36 27.75,64.52 27.75,58.86 28.77,57.85 28.77,44.77 P1.RC
MDI_CH0_N: length 22.3
  TOP w0.254: P1.2 22.17,47.05 22.35,46.86 23.84,46.86 25.5,48.52 29.87,48.52 33.53,44.86 33.53,42.99 34.95,41.57 38.05,41.57 38.4,41.22 38.4,41 38.57,40.83 T9.2
MDI_CH0_P: length 23.1
  TOP w0.254: P1.1 20.44,46.48 24,46.48 25.65,48.14 29.72,48.14 33.15,44.7 33.15,42.83 34.79,41.19 37.9,41.19 38.02,41.06 38.02,41 37.84,40.82 T9.1
MDI_CH1_N: length 18.9
  TOP w0.254: v1(24.7,49.79) 24.89,49.6 31.4,49.6 32.76,48.24 38.06,48.24 38.41,47.89 38.41,47.6 38.57,47.44 T8.2
  BOTTOM w0.254: v1(24.7,49.79) 24.51,49.6 24.19,49.6 22.8,50.99 22.42,50.99 22.17,51.24 P1.6
MDI_CH1_P: length 21.1
  TOP w0.254: T8.1 37.84,47.42 38.03,47.61 38.03,47.73 37.9,47.86 32.6,47.86 31.24,49.21 24.89,49.21 v1(24.7,49.02)
  BOTTOM w0.254: v1(24.7,49.02) 24.51,49.21 24.04,49.21 22.64,50.61 21.91,50.61 20.39,49.1 P1.3
MDI_CH2_N: length 20.9
  TOP w0.254: T7.2 38.57,54.04 38.4,54.21 38.4,54.49 38.05,54.84 35.32,54.84 31.28,50.8 23.27,50.8 22.93,50.46 20.45,50.46 P1.5
MDI_CH2_P: length 19
  TOP w0.254: P1.4 22.17,49.86 22.39,50.07 23.08,50.07 23.43,50.42 31.44,50.42 35.47,54.46 37.9,54.46 38.02,54.33 38.02,54.21 37.84,54.03 T7.1
MDI_CH3_N: length 23.7
  TOP w0.254: P1.8 22.17,53.2 22.42,52.96 24.39,52.96 25.46,51.88 29.69,51.88 33.15,55.34 33.15,58.14 36.46,61.44 38.04,61.44 38.39,61.09 38.39,60.83 38.57,60.65 T6.2
MDI_CH3_P: length 24.5
  TOP w0.254: P1.7 20.42,52.58 24.23,52.58 25.31,51.5 29.85,51.5 33.53,55.18 33.53,57.98 36.61,61.06 37.88,61.06 38.01,60.94 38.01,60.79 37.84,60.63 T6.1
PAIR12: length 34.4
  L4 w0.762: v1(58.55,21.59) 49.15,21.59 35.18,35.56 35.18,36.58 v2(35.18,36.58)
  BOTTOM w0.508: RV38.2 34.03,37.21 34.48,36.77 34.99,36.77 v2(35.18,36.58) FB23.2
  BOTTOM w0.762: v1(58.55,21.59) 58.08,22.06 D53.AC2
PAIR12_FB23:
  vias: v2(37.21,36.96) v2(37.21,36.2)
PAIR36: length 45
  L4 w0.762: v2(35.18,43.44) 34.04,42.29 34.04,35.21 48.74,20.51 57.72,20.51 58.54,19.69 v1(58.54,18.48)
  BOTTOM w0.508: FB22.2 v2(35.18,43.44) 34.41,43.44 34.03,43.82 RV37.2
  BOTTOM w0.762: v1(58.54,18.48) 58.12,18.06 D53.AC1
PAIR36_FB22:
  vias: v2(37.21,43.56) v2(37.21,42.8)
PAIR45: length 51.1
  L4 w0.762: v1(58.61,26.99) 59.63,25.97 59.63,23.18 59.12,22.67 49.59,22.67 36.32,35.94 36.32,48.65 v2(35.18,49.79)
  BOTTOM w0.508: RV36.2 34.04,49.79 v2(35.18,49.79) FB21.2
  BOTTOM w0.762: D57.AC2 57.83,27.77 v1(58.61,26.99)
PAIR45_FB21:
  vias: v2(37.21,50.17) v2(37.21,49.41)
PAIR78: length 50.8
  L4 w0.762: v2(35.05,56.64) 38.08,53.61 38.08,35.67 49.98,23.77 v1(58.55,23.77)
  BOTTOM w0.508: FB20.2 v2(35.05,56.64) 34.04,56.64 RV35.2
  BOTTOM w0.762: v1(58.55,23.77) D57.AC1
PAIR78_FB20:
  vias: v2(37.21,56.77) v2(37.21,56.01)
POE_AT_AF_DET: length 9.9
  BOTTOM w0.127: v2(95.06,62.04) 95.06,52.44 R241.2
POWER_IN:
  vias: v1(88.77,70.61) v1(88.77,69.85) v1(89.53,70.61) v1(89.53,69.85) v1(90.3,70.61) v1(90.3,69.85) v1(90.3,69.09) v1(90.3,68.33)
SS: length 1.8
  TOP w0.203: U50.33 86.51,35.68 C420.1
SYSTEM LED_B:
  vias: v2(47.06,15.04)
T2P: length 11.3
  TOP w0.203: U50.14 81.34,40.59 81.47,40.72 v2(81.47,42.74)
  BOTTOM w0.203: R322.1 86.04,48.64 81.47,44.07 v2(81.47,42.74)
UV: length 27.9
  TOP w0.203: v2(88.95,37.7) 88.86,37.79 U50.38
  L4 w0.203: v2(72.9,37.78) 76.07,40.96 87.57,40.96 88.95,39.57 v2(88.95,37.7)
  BOTTOM w0.203: R291.1 R292.2 70.24,35.51 C374.2 70.45,35.5 71.82,35.5 72.9,36.58 v2(72.9,37.78)
VB: length 10.2
  TOP w0.203: v2(90.04,37.4) 89.79,37.4 89.61,37.23 C413.1 89.15,36.77 88.53,37.39 U50.37
  L4 w0.203: v2(90.04,43.12) v2(90.04,37.4)
  BOTTOM w0.203: v2(90.04,43.12) 90.04,43.29 R317.1 R310.2
VREG: length 53
  TOP w0.381: R299.2 v2(91.57,36.07)
  TOP w0.762: C416.1 61.38,45.39 v2(62.29,45.39) D15.A 63.98,46.22 R313.2 R297.2
  L4 w0.381: v2(91.57,36.07) 91.88,36.39 91.88,47.94 89.28,50.55 66.55,50.55 62.29,46.29 v2(62.29,45.39)
N5282457: length 1.8
  TOP w0.203: v2(88.77,45.34) U41.4
  BOTTOM w0.203: v2(88.77,45.34) 88.77,44.78 R310.1
N5282939: length 2.3
  TOP w0.381: R147.2 95.07,38.86 D8.C
N5283551: length 2.7
  TOP w0.762: R313.1 65.6,47.33 T3.4
N5284275: length 5.1
  TOP w0.203: U41.3 v2(88.77,46.61)
  BOTTOM w0.203: v2(88.77,46.61) 87,46.61 86.44,46.05 R311.2 86.42,45.58 R316.2
N5284681: length 1.9
  TOP w0.203: U40.1 v2(91.06,49.91)
  BOTTOM w0.203: v2(91.06,49.91) R172.2
N5284715: length 3.4
  TOP w0.381: v2(94.87,50.74) 94.87,50.29 95.25,49.91 U40.4
  BOTTOM w0.381: R241.1 v2(94.87,50.74) R180.1
N5285307: length 2.8
  TOP w0.203: 89.91,48.64 v2(88.77,48.64)
  BOTTOM w0.203: R322.2 87.81,48.97 88.14,48.64 v2(88.77,48.64)
N5587134: length 23.4
  TOP w0.076: L47.4 44.5,42.85 44.87,43.22 45.48,43.22 46.05,43.79 46.39,43.79 D81.2 46.58,43.98 46.58,44.35 46.87,44.63 C68.1 47.2,44.94 47.35,45.09 v2(47.68,45.09)
  L4 w0.076: v2(47.68,45.09) 47.68,45.44 48.14,45.9 arc(48.77,46.83) 48.98,47.93 48.98,61.91 48.43,62.46 48.43,62.88 v2(48.68,63.13)
N5587686: length 30.3
  TOP w0.076: v2(47.67,38.51) 47.32,38.51 47.14,38.33 C70.1 46.84,38.03 46.56,37.74 46.56,37.41 D82.2 46.32,37.17 45.98,37.17 45.4,36.59 44.87,36.59 44.52,36.24 L48.4
  L4 w0.076: v2(50.97,63.13) 50.72,62.88 50.72,62.27 50.16,61.72 50.16,43.55 arc(49.76,41.52) 48.61,39.8 47.67,38.86 v2(47.67,38.51)
N5589036: length 19.5
  TOP w0.076: v2(47.18,52.2) 47.18,51.85 47.01,51.68 C65.1 46.7,51.35 46.46,51.1 46.09,51.1 D80.1 45.85,50.86 45.85,50.52 45.35,50.02 44.9,50.02 44.54,50.38 L46.1
  L4 w0.076: v2(47.18,52.2) 47.53,52.2 47.62,52.29 47.62,56.97 47.58,57.02 47.53,57.07 47.53,57.22 47.58,57.27 47.62,57.32 47.62,57.47 47.58,57.52 47.53,57.56 47.53,57.72 47.58,57.76 47.62,57.81 47.62,57.96 47.58,58.01 47.53,58.06 47.53,58.21 47.58,58.26 47.62,58.31 47.62,59.15 47.47,59.31 46.81,59.31 46.46,59.66 46.46,60.35 46.77,60.67 47.6,60.67 47.76,60.83 47.76,61.37 47.56,61.56 46.32,61.56 45.93,61.96 45.93,62.88 v2(45.68,63.13)
N17072113: length 3.7
  TOP w0.381: D61.1 44.26,60.18 C434.2 C400.2 40.58,60.18 T6.3
N17072503: length 19.4
  TOP w0.076: L45.1 44.54,56.98 44.9,56.63 46.12,56.63 46.4,56.34 46.4,56.09 46.64,55.85 D79.1 46.64,55.53 46.4,55.29 46.4,54.89 C63.1 46.4,54.45 46.4,54.3 v2(46.65,54.05)
  L4 w0.076: v2(43.99,63.13) 44.24,62.88 44.24,62.1 45.15,61.19 45.15,60.8 44.96,60.61 44.02,60.61 43.66,60.26 43.66,59.66 44.55,58.77 44.55,53.63 45.06,53.12 46,53.12 46.4,53.52 46.4,53.8 v2(46.65,54.05)
N17072520: length 19.3
  TOP w0.076: L45.4 44.55,56.05 44.9,56.41 46.03,56.41 46.18,56.25 46.18,56.09 45.94,55.85 D79.2 45.94,55.53 46.18,55.29 46.18,54.89 C64.1 46.18,54.45 46.18,54.3 v2(45.94,54.05)
  L4 w0.076: v2(44.71,63.13) 44.46,62.88 44.46,62.19 44.6,62.05 44.73,62.05 44.84,61.94 44.84,61.81 44.94,61.7 45.07,61.7 45.18,61.6 45.18,61.47 45.36,61.28 45.36,60.71 45.05,60.39 44.11,60.39 43.88,60.17 43.88,59.75 44.02,59.61 44.15,59.61 44.26,59.5 44.26,59.37 44.37,59.27 44.49,59.27 44.6,59.16 44.6,59.03 44.77,58.86 44.77,58.62 44.81,58.57 44.82,58.57 44.86,58.52 44.86,58.37 44.82,58.32 44.81,58.32 44.77,58.28 44.77,58.12 44.81,58.08 44.82,58.08 44.86,58.03 44.86,57.88 44.82,57.83 44.81,57.83 44.77,57.78 44.77,57.63 44.81,57.58 44.82,57.58 44.86,57.53 44.86,57.38 44.82,57.33 44.81,57.33 44.77,57.29 44.77,57.13 44.81,57.09 44.82,57.09 44.86,57.04 44.86,56.89 44.82,56.84 44.81,56.84 44.77,56.79 44.77,56.64 44.81,56.59 44.82,56.59 44.86,56.54 44.86,56.39 44.82,56.34 44.81,56.34 44.77,56.3 44.77,56.14 44.81,56.1 44.82,56.1 44.86,56.05 44.86,55.9 44.82,55.85 44.81,55.85 44.77,55.8 44.77,55.65 44.81,55.6 44.82,55.6 44.86,55.55 44.86,55.4 44.82,55.35 44.81,55.35 44.77,55.31 44.77,55.15 44.81,55.11 44.82,55.11 44.86,55.06 44.86,54.91 44.82,54.86 44.81,54.86 44.77,54.81 44.77,54.66 44.81,54.61 44.82,54.61 44.86,54.56 44.86,54.41 44.82,54.36 44.81,54.36 44.77,54.32 44.77,53.72 45.15,53.34 45.91,53.34 46.18,53.61 46.18,53.8 v2(45.94,54.05)
N17072536: length 4
  TOP w0.076: T6.4 40.64,56.09 40.39,55.83 40.39,55.73 40.45,55.67 40.97,55.67 41.05,55.75 41.15,55.75 41.23,55.67 41.35,55.67 41.47,55.78 41.47,55.91 41.37,56.01 41.37,56.17 41.47,56.26 41.47,56.42 41.67,56.63 42.02,56.63 42.37,56.98 L45.2
N17072544: length 4.1
  TOP w0.076: T6.5 39.92,56.08 40.17,55.83 40.17,55.64 40.36,55.45 41.44,55.45 41.68,55.7 41.68,56.33 41.76,56.41 42.02,56.41 42.37,56.05 L45.3
N17073401: length 3.7
  TOP w0.381: D62.1 44.26,53.58 C450.2 C401.2 40.58,53.58 T7.3
N17073788: length 19.6
  TOP w0.076: L46.4 44.52,49.45 44.88,49.81 45.44,49.81 46,50.37 46.34,50.37 D80.2 46.58,50.61 46.58,50.93 46.88,51.22 C66.1 47.16,51.53 47.33,51.69 v2(47.68,51.69)
  L4 w0.076: v2(46.39,63.13) 46.15,62.88 46.15,62.05 46.41,61.78 47.65,61.78 47.97,61.46 47.97,60.74 47.69,60.45 46.86,60.45 46.67,60.26 46.67,59.75 46.9,59.52 47.56,59.52 47.84,59.24 47.84,52.2 47.68,52.04 v2(47.68,51.69)
N17073817: length 4
  TOP w0.076: T7.4 40.64,49.48 40.39,49.23 40.39,49.13 40.45,49.06 40.97,49.06 41.05,49.15 41.15,49.15 41.23,49.06 41.35,49.06 41.47,49.18 41.47,49.31 41.37,49.4 41.37,49.56 41.47,49.66 41.47,49.82 41.67,50.02 42.02,50.02 42.37,50.38 L46.2
N17073825: length 4.1
  TOP w0.076: T7.5 39.92,49.48 40.17,49.23 40.17,49.04 40.36,48.85 41.44,48.85 41.68,49.09 41.68,49.73 41.76,49.81 42.02,49.81 42.37,49.45 L46.3
N17074521: length 3.8
  TOP w0.381: D63.1 44.32,46.98 C451.2 C402.2 40.58,46.98 T8.3
N17074761: length 23.3
  TOP w0.076: L47.1 44.56,43.77 44.89,43.43 45.39,43.43 45.9,43.95 45.9,44.29 D81.1 46.12,44.51 46.44,44.51 46.74,44.81 C67.1 47.04,45.09 47.18,45.23 v2(47.18,45.59)
  L4 w0.076: v2(47.18,45.59) 47.53,45.59 47.99,46.05 arc(48.57,46.91) 48.77,47.93 48.77,59.68 48.72,59.73 48.67,59.78 48.67,59.93 48.72,59.98 48.77,60.02 48.77,60.18 48.72,60.22 48.67,60.27 48.67,60.42 48.72,60.47 48.77,60.52 48.77,60.67 48.72,60.72 48.67,60.77 48.67,60.92 48.72,60.97 48.77,61.01 48.77,61.17 48.72,61.21 48.67,61.26 48.67,61.41 48.72,61.46 48.77,61.51 48.77,61.82 48.22,62.37 48.22,62.88 v2(47.97,63.13)
N17074791: length 4
  TOP w0.076: L47.2 42.37,43.77 42.02,43.42 41.67,43.42 41.47,43.21 41.47,43.05 41.37,42.96 41.37,42.8 41.47,42.7 41.47,42.58 41.35,42.46 41.23,42.46 41.15,42.55 41.05,42.55 40.97,42.46 40.45,42.46 40.39,42.52 40.39,42.62 40.64,42.88 T8.4
N17075150: length 3.7
  TOP w0.381: D64.1 44.26,40.37 C452.2 C403.2 40.58,40.37 T9.3
N17075378: length 30.3
  TOP w0.076: v2(47.17,39.01) 47.17,38.66 46.99,38.49 C69.1 46.68,38.17 46.42,37.91 46.07,37.91 45.82,37.66 45.82,37.32 45.31,36.8 44.88,36.8 44.52,37.17 L48.1
  L4 w0.076: v2(47.17,39.01) 47.52,39.01 48.46,39.96 arc(49.56,41.61) 49.95,43.55 49.95,60.02 49.85,60.12 49.85,60.27 49.95,60.37 49.95,60.53 49.85,60.63 49.85,60.78 49.95,60.88 49.95,61.03 49.85,61.14 49.85,61.29 49.95,61.39 49.95,61.81 50.5,62.36 50.5,62.88 v2(50.25,63.13)
N17075450: length 4
  TOP w0.076: T9.4 40.64,36.28 40.39,36.02 40.39,35.92 40.45,35.85 40.97,35.85 41.05,35.94 41.15,35.94 41.23,35.85 41.35,35.85 41.47,35.97 41.47,36.1 41.37,36.2 41.37,36.35 41.47,36.45 41.47,36.61 41.67,36.81 42.02,36.81 42.37,37.17 L48.2
N17075458: length 4.1
  TOP w0.076: L48.3 42.37,36.24 42.02,36.6 41.76,36.6 41.68,36.52 41.68,35.88 41.44,35.64 40.36,35.64 40.17,35.83 40.17,36.02 39.92,36.27 T9.5
N17430841: length 2
  TOP w0.381: R141.1 96.57,45.17 U41.1
N17430844: length 1.9
  TOP w0.381: D8.A 95.2,41.96 R141.2
N17432448:
  vias: v1(65.15,72.01) v1(65.6,72.71) v1(66.04,72.01) v1(66.48,72.71) v1(66.87,72.01) v1(67.31,72.71) v1(67.69,72.01) v1(68.14,72.71) v1(68.58,72.01)
N17432813:
  vias: v1(84.71,69.85) v1(84.71,68.96) v1(84.71,68.07) v1(84.71,67.18) v1(85.47,67.18) v1(85.6,69.85) v1(86.36,69.85) v1(86.36,67.18)
N17439497: length 7
  TOP w0.203: U50.34 86.91,35.96 87.38,35.5 87.82,35.5 88.14,35.18 88.14,34.61 88.63,34.11 C412.2 89.6,34.11 R301.1 89.61,33.43 R300.2 R298.1
N17439527: length 0.9
  TOP w0.203: C410.2 R301.2
N17439559: length 3.2
  TOP w0.203: C410.1 89.6,34.97 C412.1 88.71,35.18 87.95,35.94 87.5,35.94 87.31,36.13 U50.35
N17439609: length 2
  TOP w0.203: U50.36 88.36,36.99 89.47,35.88 R302.2
N17439796: length 1.6
  TOP w0.203: U50.39 89.46,38.19 R336.1
N17439853: length 4
  TOP w0.381: D5.A 86.82,45.8 R303.1 83.52,45.8 83.38,45.66 Q3.4
N17439860: length 14.6
  TOP w0.203: 89.03,39.94 88.87,39.79 U50.43
  TOP w0.381: R303.2 85.83,47.16 86.23,47.56 86.23,48.36 D5.C 87.22,48.99 88.01,48.2 88.01,45.09 89.03,44.07 89.03,42.74 89.6,42.16 89.6,40.51 89.03,39.94
N17440114: length 2.5
  TOP w0.381: R148.1 95.76,32.86 95.89,32.73 95.89,31.24 96.01,31.11 U42.2
N17440204: length 21.1
  TOP w0.381: v2(89.41,28.96) 89.41,29.72 89.53,29.84 U42.4
  BOTTOM w0.381: R151.1 79.32,35.69 R149.2 78.87,34.74 77.6,33.46 77.6,29.84 78.49,28.96 v2(89.41,28.96)
N17440325: length 1.5
  TOP w0.203: U50.17 80.1,39.39 R294.1
N17440336: length 1.6
  TOP w0.203: R307.1 79.97,37.79 U50.21
N17440344: length 1.7
  TOP w0.203: v1(82.68,35.69) 82.51,35.85 U50.24
  BOTTOM w0.381: R151.2 v1(82.68,35.69)
N17440357: length 1.6
  TOP w0.203: R296.2 86.11,34.77 U50.32
N17440451: length 2
  BOTTOM w0.381: C746.1 89.84,39 R314.2
N17440486: length 1.4
  TOP w0.203: U50.11 82.91,42.57 R315.1
N17440571: length 1.3
  TOP w0.203: R299.1 91.57,32.85 R298.2
N17440589: length 1.6
  TOP w0.203: U50.40 89.28,38.59 C745.1
N17592466: length 1.2
  TOP w0.635: R83.2 85.09,51.04 C72.1
N17603237: length 4.1
  TOP w0.076: L47.3 42.37,42.85 42.02,43.2 41.76,43.2 41.68,43.12 41.68,42.49 41.44,42.24 40.36,42.24 40.17,42.43 40.17,42.62 39.92,42.88 T8.5
N51055004: length 26.7
  BOTTOM w0.508: 38.34,51.44 35.75,51.44 C26.1 ; 38.34,51.44 R237.2 ; 38.34,51.44 R243.2 R244.2 38.35,39.35 R242.2 36.28,37.96 35.56,38.67 35.56,40.32 34.73,41.15 C25.1
N51058661: length 1.3
  BOTTOM w0.508: R237.1 36.97,53.85 C238.1
N51058667: length 1.3
  BOTTOM w0.508: R243.1 36.97,47.25 C361.1
N51058675: length 1.3
  BOTTOM w0.508: C363.1 36.96,39.39 R244.1
N51058681: length 1.2
  BOTTOM w0.508: C367.1 38.35,35.39 R242.1

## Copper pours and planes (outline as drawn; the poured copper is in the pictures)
GND on TOP (solid shape): 99.45,29.6 98.65,29.6 98.65,69.2 99.45,69.2
GND on TOP (solid shape): 51.21,25.35 53.98,25.35 53.98,24.55 50.41,24.55 50.41,33.27 51.21,33.27
GND on TOP (solid shape): 58.23,56.45 51.21,56.45 51.21,35.81 50.41,35.81 50.41,57.25 58.23,57.25
GND on TOP (solid shape): 99.45,24.55 90.81,24.55 90.81,25.35 98.65,25.35 98.65,27 99.45,27
GND on TOP (solid shape): 99.45,71.8 98.65,71.8 98.65,73.45 58.23,73.45 58.23,59.9 57.43,59.9 57.43,74.25 99.45,74.25
GND on BOTTOM (solid shape): 51.19,15.39 64.59,15.39 64.59,14.59 50.39,14.59 50.39,33.25 51.19,33.25
GND on BOTTOM (solid shape): 97.69,54.85 96.89,54.85 96.89,78.49 80.59,78.49 80.59,79.29 97.69,79.29
GND on BOTTOM (solid shape): 78.19,78.49 61.61,78.49 61.61,54.49 51.19,54.49 51.19,35.65 50.39,35.65 50.39,55.29 60.81,55.29 60.81,79.29 78.19,79.29
GND on BOTTOM (solid shape): 97.69,24.47 91.72,24.47 91.72,14.59 66.99,14.59 66.99,15.39 90.92,15.39 90.92,25.27 96.89,25.27 96.89,52.2 97.69,52.2
GND on TOP: 55.69,81.52 102.32,81.52 102.32,13.82 16.51,13.82 16.51,36.2 27.56,36.2 29.34,34.42 31.88,34.42 33.4,32.89 39.31,32.89 39.69,33.27 39.69,36.96 39.88,37.15 40.96,37.15 41.15,37.34 41.15,41.15 39.69,42.61 39.69,43.56 39.88,43.75 40.96,43.75 41.15,43.94 41.15,47.75 39.69,49.21 39.69,50.36 40.96,50.36 41.15,50.55 41.15,54.36 39.69,55.82 39.69,56.77 39.88,56.96 40.96,56.96 41.15,57.15 41.15,62.23 40.01,63.37 25.4,63.37 22.48,60.45 16.51,60.45 16.51,68.63 55.31,68.63 55.31,68.7 55.69,68.7 ; 1 cut-out
GND on BOTTOM: 58.5,81.52 102.32,81.52 102.32,13.82 16.51,13.82 16.51,36.2 27.56,36.2 29.34,34.42 31.88,34.42 33.4,32.89 40.13,32.89 41.15,33.91 41.15,60.58 40.01,61.72 36.07,61.72 34.42,63.37 25.4,63.37 22.48,60.45 16.51,60.45 16.51,68.46 58.5,68.46 ; 1 cut-out
GND on L2: 55.69,81.52 102.32,81.52 102.32,13.82 16.51,13.82 16.51,36.2 27.56,36.2 29.34,34.42 31.88,34.42 48.01,18.29 53.98,18.29 53.98,14.86 90.81,14.86 90.81,25.4 94.11,25.4 94.11,53.72 53.98,53.72 53.98,26.16 50.48,26.16 41.21,35.43 40.26,35.43 39.69,36 39.69,36.96 39.88,37.15 40.96,37.15 41.15,37.34 41.15,41.15 39.69,42.61 39.69,43.56 39.88,43.75 40.96,43.75 41.15,43.94 41.15,47.75 39.69,49.21 39.69,50.16 39.88,50.36 40.96,50.36 41.15,50.55 41.15,54.36 39.69,55.82 39.69,56.77 39.88,56.96 40.96,56.96 41.15,57.15 41.15,62.23 40.01,63.37 25.4,63.37 22.48,60.45 16.51,60.45 16.51,68.63 55.31,68.63 55.31,68.7 55.69,68.7
GND on L2: 55.69,81.52 102.32,81.52 102.32,13.82 16.51,13.82 16.51,36.2 27.56,36.2 29.34,34.42 31.88,34.42 48.01,18.29 53.98,18.29 53.98,26.16 50.48,26.16 41.21,35.43 40.26,35.43 39.69,36 39.69,36.96 39.88,37.15 40.96,37.15 41.15,37.34 41.15,41.15 39.69,42.61 39.69,43.56 39.88,43.75 40.96,43.75 41.15,43.94 41.15,47.75 39.69,49.21 39.69,50.16 39.88,50.36 40.96,50.36 41.15,50.55 41.15,54.36 39.69,55.82 39.69,56.77 39.88,56.96 40.96,56.96 41.15,57.15 41.15,62.23 40.01,63.37 25.4,63.37 22.48,60.45 16.51,60.45 16.51,68.63 55.31,68.63 55.31,68.7 55.69,68.7
GND on L3: 55.69,81.52 102.32,81.52 102.32,13.82 16.51,13.82 16.51,36.2 27.56,36.2 29.34,34.42 31.88,34.42 48.01,18.29 53.98,18.29 53.98,15.37 90.81,15.37 90.81,25.4 94.11,25.4 94.11,53.72 53.98,53.72 53.98,26.16 50.48,26.16 41.21,35.43 40.26,35.43 39.69,36 39.69,36.96 39.88,37.15 40.96,37.15 41.15,37.34 41.15,41.15 39.69,42.61 39.69,43.56 39.88,43.75 40.96,43.75 41.15,43.94 41.15,47.75 39.69,49.21 39.69,50.16 39.88,50.36 40.96,50.36 41.15,50.55 41.15,54.36 39.69,55.82 39.69,56.77 39.88,56.96 40.96,56.96 41.15,57.15 41.15,62.23 40.01,63.37 25.4,63.37 22.48,60.45 16.51,60.45 16.51,68.63 55.31,68.63 55.31,68.7 55.69,68.7
GND on L3: 26.29,63.63 26.29,53.59 27.18,52.7 27.18,47.12 26.42,46.35 26.42,42.16 27.18,41.4 27.18,34.42 29.08,34.42 29.08,57.98 28,59.05 28,63.63
GND on L4, L5: 55.69,81.52 102.32,81.52 102.32,13.82 16.51,13.82 16.51,36.2 27.56,36.2 29.34,34.42 31.88,34.42 48.01,18.29 53.98,18.29 53.98,26.16 50.48,26.16 41.15,35.5 41.15,60.58 40.01,61.72 36.07,61.72 34.42,63.37 25.4,63.37 22.48,60.45 16.51,60.45 16.51,68.63 55.31,68.63 55.31,68.7 55.69,68.7
PGND on TOP (solid shape): 87.63,33.34 88.01,33.34 88.01,32.13 88.33,31.81 88.33,28.13 86.36,28.13 86.36,31.24 85.66,31.94 85.66,33.78 86.93,33.78 86.93,34.16 87.63,34.16
PGND on TOP: 56.01,51.69 56.01,16.89 88.77,16.89 88.77,27.43 92.08,27.43 92.08,51.69 ; 1 cut-out
PGND on BOTTOM: 56.01,51.69 56.01,16.89 88.77,16.89 88.77,27.43 92.08,27.43 92.08,51.69 ; 2 cut-outs
PGND on L2, L3, L5: 56.01,51.69 56.01,16.89 88.77,16.89 88.77,27.43 92.08,27.43 92.08,51.69
PGND on L4: 56.01,51.69 56.01,16.89 88.77,16.89 88.77,27.43 92.08,27.43 92.08,51.69 ; 3 cut-outs
VCC_3V3 on TOP (solid shape): 56.32,65.79 56.32,64.39 56.2,64.26 54.29,64.26 54.17,64.39 54.17,65.85 54.23,65.92 56.2,65.92
VCC_3V3 on L2: 101.73,51.31 102.32,51.31 102.32,22.18 101.73,21.59 100.33,21.59 99.57,20.83 99.57,17.4 97.66,15.49 97.66,13.82 92.71,13.82 92.71,21.46 99.06,27.81 99.06,48.64
VCC_3V7 on L2: 102.11,20.83 102.32,21.04 102.32,19.47 102.11,19.68 100.58,19.68 100.33,19.94 100.33,20.57 100.58,20.83
VCC_9_15V on TOP (solid shape): 95.5,70.87 95.5,67.06 95.25,66.8 91.95,66.8 91.69,67.06 91.69,70.87 91.95,71.12 95.25,71.12
VCC_9_15V on BOTTOM (solid shape): 95.63,70.87 95.63,65.53 95.5,65.41 94.49,65.41 94.23,65.15 94.23,63.31 94.04,63.12 93.6,63.12 93.54,63.18 93.54,63.63 93.73,63.82 93.73,70.87 93.85,70.99 95.5,70.99
VCC_9_15V on L2: 95.76,76.33 102.32,76.33 102.32,72.64 99.57,72.64 98.17,71.25 98.17,68.2 97.41,67.44 93.85,67.44 93.47,67.82 93.47,74.04
VDD_B on TOP (solid shape): 62.36,44.07 62.36,34.16 62.87,33.66 66.8,33.66 66.8,28.19 60.96,28.19 57.28,31.88 57.28,37.59 57.53,37.85 57.53,43.94 57.78,44.2 62.23,44.2
VDD_B on TOP (solid shape): 82.2,34.45 81.66,33.91 77.91,33.91 77.34,33.34 77.34,32.07 76.58,31.31 76.58,28.45 76.33,28.19 66.44,28.19 66.44,33.66 72.64,33.66 75.31,36.32 81.69,36.32 82.01,36.64 82.2,36.64
VDD_B on BOTTOM (solid shape): 76.58,32.89 76.58,31.5 76.33,31.24 73.53,31.24 73.28,31.5 73.28,32.89 73.53,33.15 76.33,33.15
VDD_B on BOTTOM (solid shape): 87.38,24.38 87.38,21.72 87.25,21.59 82.49,21.59 82.17,21.27 78.87,21.27 78.74,21.4 78.74,21.65 78.49,21.91 76.14,21.91 76.01,22.03 76.01,24.38 76.2,24.57 87.19,24.57
